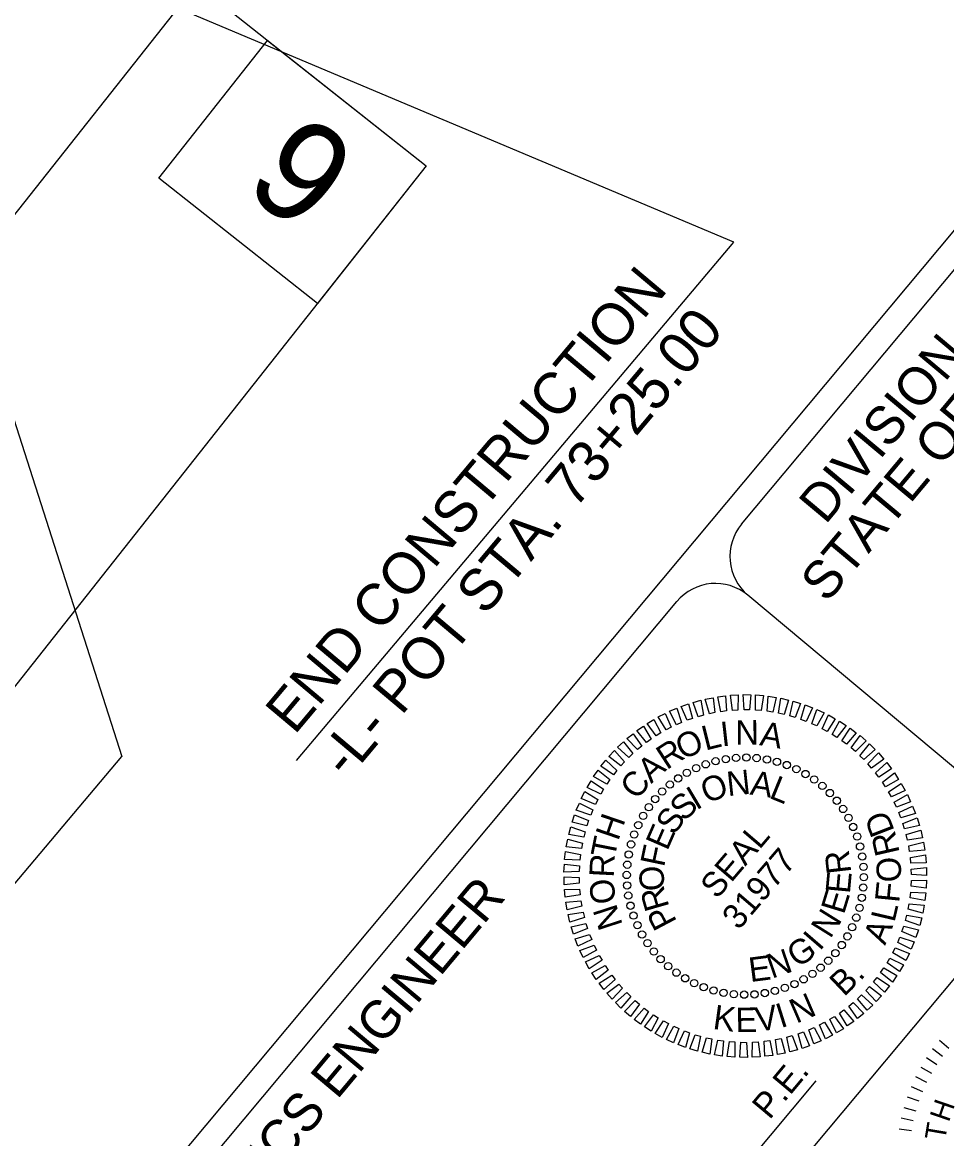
# Model space of a CAD drawing. Extents: x 555292 to 2368606, y 503623 to 1171444.
# Drawn here: x 2362561 to 2363476, y 1164815 to 1165919 of the extents above; entities that cross this region are included whole.
import ezdxf

# ---------------------------------------------------------------- set-up
doc = ezdxf.new("R2010")
doc.units = 0
for name, color, linetype in [('Default', 7, 'Continuous'), ('Old_Level_21', 7, 'Continuous'), ('Prop Horizontal Alignment Station Label', 7, 'Continuous'), ('Sheet Title CELL', 7, 'Continuous')]:
    doc.layers.add(name, color=color, linetype=linetype)

msp = doc.modelspace()

# ---------------------------------------------------------------- linework, layer by layer
at = {"layer": 'Default'}
for points in [[(2363263.9, 1165238.4), (2363261.9, 1165253.4), (2363269.7, 1165253.7), (2363269.4, 1165238.8)], [(2363275.4, 1165238.9), (2363274.4, 1165254), (2363282.2, 1165253.8), (2363280.9, 1165238.9)], [(2363286.9, 1165238.6), (2363286.9, 1165253.7), (2363294.7, 1165253), (2363292.4, 1165238.2)], [(2363219.2, 1165228.6), (2363213.1, 1165242.4), (2363220.5, 1165244.9), (2363224.4, 1165230.5)], [(2363230.1, 1165232.2), (2363225, 1165246.4), (2363232.6, 1165248.4), (2363235.4, 1165233.7)], [(2363241.2, 1165235.1), (2363237.1, 1165249.6), (2363244.8, 1165251), (2363246.6, 1165236.2)], [(2363252.5, 1165237.1), (2363249.4, 1165251.9), (2363257.2, 1165252.8), (2363258, 1165237.9)], [(2363298.3, 1165237.5), (2363299.4, 1165252.6), (2363307.1, 1165251.3), (2363303.8, 1165236.7)], [(2363309.6, 1165235.6), (2363311.7, 1165250.5), (2363319.4, 1165248.7), (2363315, 1165234.4)], [(2363320.8, 1165232.9), (2363323.9, 1165247.7), (2363331.4, 1165245.3), (2363326.1, 1165231.4)], [(2363331.7, 1165229.4), (2363335.9, 1165243.9), (2363343.2, 1165241.1), (2363336.9, 1165227.5)], [(2363198.3, 1165219.1), (2363190.4, 1165231.9), (2363197.4, 1165235.4), (2363203.2, 1165221.7)], [(2363208.6, 1165224.2), (2363201.6, 1165237.5), (2363208.8, 1165240.5), (2363213.7, 1165226.4)], [(2363342.4, 1165225.2), (2363347.6, 1165239.4), (2363354.6, 1165236), (2363347.4, 1165223)], [(2363352.7, 1165220.3), (2363358.9, 1165234), (2363365.7, 1165230.2), (2363357.6, 1165217.7)], [(2363179, 1165206.8), (2363169.3, 1165218.4), (2363175.8, 1165222.8), (2363183.5, 1165210)], [(2363188.4, 1165213.3), (2363179.6, 1165225.5), (2363186.3, 1165229.5), (2363193.1, 1165216.2)], [(2363362.7, 1165214.6), (2363369.8, 1165227.9), (2363376.4, 1165223.6), (2363367.4, 1165211.7)], [(2363372.3, 1165208.3), (2363380.3, 1165221), (2363386.5, 1165216.3), (2363376.7, 1165205)], [(2363170, 1165199.6), (2363159.5, 1165210.5), (2363165.7, 1165215.4), (2363174.2, 1165203.2)], [(2363381.4, 1165201.3), (2363390.3, 1165213.5), (2363396.1, 1165208.3), (2363385.6, 1165197.7)], [(2363153.6, 1165183.6), (2363141.7, 1165192.9), (2363147.1, 1165198.6), (2363157.3, 1165187.7)], [(2363161.5, 1165191.9), (2363150.3, 1165202), (2363156.1, 1165207.3), (2363165.5, 1165195.7)], [(2363390, 1165193.6), (2363399.7, 1165205.2), (2363405.2, 1165199.6), (2363393.9, 1165189.8)], [(2363146.3, 1165174.7), (2363133.8, 1165183.2), (2363138.8, 1165189.2), (2363149.7, 1165179.1)], [(2363398, 1165185.5), (2363408.5, 1165196.3), (2363413.6, 1165190.3), (2363401.7, 1165181.3)], [(2363139.6, 1165165.4), (2363126.6, 1165173), (2363131.1, 1165179.3), (2363142.7, 1165170)], [(2363405.5, 1165176.7), (2363416.7, 1165186.8), (2363421.3, 1165180.5), (2363408.8, 1165172.4)], [(2363412.3, 1165167.5), (2363424.2, 1165176.7), (2363428.4, 1165170.1), (2363415.3, 1165162.9)], [(2363133.6, 1165155.6), (2363120.1, 1165162.3), (2363124.2, 1165168.9), (2363136.4, 1165160.4)], [(2363418.4, 1165157.8), (2363431, 1165166.2), (2363434.7, 1165159.3), (2363421.2, 1165153)], [(2363128.3, 1165145.4), (2363114.3, 1165151.1), (2363117.9, 1165158.1), (2363130.7, 1165150.4)], [(2363423.9, 1165147.7), (2363437, 1165155.2), (2363440.2, 1165148.1), (2363426.3, 1165142.7)], [(2363123.7, 1165134.9), (2363109.4, 1165139.6), (2363112.5, 1165146.8), (2363125.8, 1165140)], [(2363428.6, 1165137.3), (2363442.2, 1165143.8), (2363445, 1165136.5), (2363430.7, 1165132.1)], [(2363119.9, 1165124.1), (2363105.2, 1165127.8), (2363107.8, 1165135.2), (2363121.6, 1165129.4)], [(2363116.8, 1165113), (2363101.9, 1165115.7), (2363104, 1165123.2), (2363118.1, 1165118.4)], [(2363432.6, 1165126.5), (2363446.7, 1165132.1), (2363448.9, 1165124.6), (2363434.3, 1165121.2)], [(2363114.5, 1165101.8), (2363099.5, 1165103.4), (2363101, 1165111.1), (2363115.5, 1165107.2)], [(2363435.9, 1165115.5), (2363450.3, 1165120.1), (2363452, 1165112.5), (2363437.2, 1165110.1)], [(2363438.4, 1165104.3), (2363453, 1165107.9), (2363454.2, 1165100.2), (2363439.3, 1165098.8)], [(2363113, 1165090.4), (2363097.9, 1165091), (2363098.9, 1165098.7), (2363113.6, 1165095.9)], [(2363440.1, 1165092.9), (2363454.9, 1165095.5), (2363455.5, 1165087.7), (2363440.6, 1165087.4)], [(2363112.3, 1165079), (2363097.2, 1165078.5), (2363097.7, 1165086.3), (2363112.5, 1165084.5)], [(2363440.9, 1165081.5), (2363456, 1165083), (2363456, 1165075.2), (2363441.1, 1165076)], [(2363112.4, 1165067.5), (2363097.3, 1165066), (2363097.3, 1165073.8), (2363112.2, 1165073)], [(2363441, 1165070), (2363456.1, 1165070.5), (2363455.6, 1165062.7), (2363440.8, 1165064.5)], [(2363113.2, 1165056), (2363098.4, 1165053.5), (2363097.8, 1165061.3), (2363112.7, 1165061.5)], [(2363440.3, 1165058.6), (2363455.4, 1165058), (2363454.4, 1165050.2), (2363439.7, 1165053.1)], [(2363114.9, 1165044.7), (2363100.3, 1165041.1), (2363099.1, 1165048.8), (2363114, 1165050.1)], [(2363438.8, 1165047.2), (2363453.8, 1165045.6), (2363452.3, 1165037.9), (2363437.8, 1165041.7)], [(2363117.4, 1165033.5), (2363103, 1165028.9), (2363101.3, 1165036.5), (2363116.1, 1165038.8)], [(2363436.5, 1165035.9), (2363451.4, 1165033.3), (2363449.3, 1165025.7), (2363435.2, 1165030.6)], [(2363120.6, 1165022.5), (2363106.6, 1165016.9), (2363104.4, 1165024.4), (2363119, 1165027.7)], [(2363433.4, 1165024.9), (2363448.1, 1165021.2), (2363445.5, 1165013.8), (2363431.7, 1165019.6)], [(2363124.7, 1165011.7), (2363111.1, 1165005.1), (2363108.3, 1165012.5), (2363122.6, 1165016.8)], [(2363429.6, 1165014.1), (2363443.9, 1165009.3), (2363440.8, 1165002.2), (2363427.5, 1165008.9)], [(2363129.4, 1165001.3), (2363116.3, 1164993.8), (2363113.1, 1165000.9), (2363127, 1165006.2)], [(2363425, 1165003.5), (2363439, 1164997.8), (2363435.4, 1164990.9), (2363422.6, 1164998.6)], [(2363134.9, 1164991.2), (2363122.3, 1164982.8), (2363118.6, 1164989.6), (2363132.1, 1164996)], [(2363419.7, 1164993.4), (2363433.2, 1164986.7), (2363429.1, 1164980), (2363416.9, 1164988.6)], [(2363141, 1164981.5), (2363129.1, 1164972.2), (2363124.9, 1164978.8), (2363138, 1164986.1)], [(2363413.7, 1164983.6), (2363426.7, 1164976), (2363422.2, 1164969.6), (2363410.6, 1164979)], [(2363147.8, 1164972.3), (2363136.6, 1164962.2), (2363132, 1164968.5), (2363144.5, 1164976.6)], [(2363155.3, 1164963.5), (2363144.8, 1164952.7), (2363139.7, 1164958.6), (2363151.6, 1164967.6)], [(2363407, 1164974.2), (2363419.5, 1164965.8), (2363414.5, 1164959.7), (2363403.6, 1164969.9)], [(2363163.3, 1164955.3), (2363153.6, 1164943.8), (2363148.1, 1164949.4), (2363159.4, 1164959.2)], [(2363391.8, 1164957.1), (2363403, 1164946.9), (2363397.2, 1164941.7), (2363387.8, 1164953.2)], [(2363399.7, 1164965.4), (2363411.6, 1164956.1), (2363406.2, 1164950.4), (2363396, 1164961.3)], [(2363171.9, 1164947.7), (2363163, 1164935.5), (2363157.2, 1164940.7), (2363167.7, 1164951.3)], [(2363383.3, 1164949.3), (2363393.8, 1164938.4), (2363387.6, 1164933.6), (2363379.1, 1164945.8)], [(2363181, 1164940.7), (2363173, 1164927.9), (2363166.8, 1164932.7), (2363176.6, 1164944)], [(2363190.6, 1164934.4), (2363183.5, 1164921.1), (2363176.9, 1164925.4), (2363185.9, 1164937.3)], [(2363364.9, 1164935.7), (2363373.7, 1164923.5), (2363367, 1164919.5), (2363360.2, 1164932.8)], [(2363374.3, 1164942.2), (2363384, 1164930.6), (2363377.5, 1164926.2), (2363369.8, 1164939)], [(2363200.6, 1164928.7), (2363194.4, 1164914.9), (2363187.6, 1164918.8), (2363195.7, 1164931.3)], [(2363210.9, 1164923.8), (2363205.7, 1164909.6), (2363198.7, 1164913), (2363205.9, 1164926)], [(2363344.7, 1164924.8), (2363351.7, 1164911.4), (2363344.5, 1164908.4), (2363339.6, 1164922.5)], [(2363355, 1164929.9), (2363362.9, 1164917.1), (2363355.9, 1164913.6), (2363350.1, 1164927.3)], [(2363221.6, 1164919.5), (2363217.4, 1164905), (2363210.1, 1164907.9), (2363216.4, 1164921.4)], [(2363232.5, 1164916.1), (2363229.4, 1164901.3), (2363221.9, 1164903.7), (2363227.2, 1164917.6)], [(2363243.7, 1164913.4), (2363241.5, 1164898.4), (2363233.9, 1164900.3), (2363238.3, 1164914.5)], [(2363255, 1164911.5), (2363253.9, 1164896.4), (2363246.2, 1164897.7), (2363249.5, 1164912.3)], [(2363300.8, 1164911.8), (2363303.9, 1164897), (2363296.1, 1164896.2), (2363295.3, 1164911.1)], [(2363312.1, 1164913.9), (2363316.2, 1164899.4), (2363308.5, 1164898), (2363306.7, 1164912.8)], [(2363323.2, 1164916.8), (2363328.3, 1164902.6), (2363320.7, 1164900.6), (2363317.9, 1164915.3)], [(2363334.1, 1164920.4), (2363340.2, 1164906.6), (2363332.8, 1164904.1), (2363328.9, 1164918.5)], [(2363266.4, 1164910.4), (2363266.4, 1164895.3), (2363258.6, 1164896), (2363260.9, 1164910.8)], [(2363277.9, 1164910), (2363278.9, 1164895), (2363271.1, 1164895.2), (2363272.4, 1164910.1)], [(2363289.4, 1164910.5), (2363291.4, 1164895.6), (2363283.6, 1164895.2), (2363283.9, 1164910.2)]]:
    msp.add_lwpolyline(points, close=True, dxfattribs=at)
for centre in [(2363237.5, 1165185.1), (2363247.3, 1165188.1), (2363257.3, 1165190.2), (2363267.5, 1165191.4), (2363277.7, 1165191.8), (2363287.9, 1165191.3), (2363298.1, 1165189.8), (2363308, 1165187.5), (2363317.8, 1165184.4), (2363218.9, 1165176.6), (2363228, 1165181.3), (2363327.2, 1165180.4), (2363336.2, 1165175.5), (2363202.1, 1165165), (2363210.2, 1165171.2), (2363344.8, 1165170), (2363352.9, 1165163.7), (2363187.5, 1165150.7), (2363194.5, 1165158.2), (2363360.4, 1165156.7), (2363181.2, 1165142.6), (2363367.2, 1165149.1), (2363373.4, 1165140.9), (2363175.6, 1165134.1), (2363378.8, 1165132.2), (2363170.8, 1165125), (2363383.4, 1165123.1), (2363166.8, 1165115.6), (2363387.3, 1165113.6), (2363161.3, 1165095.9), (2363163.6, 1165105.9), (2363390.2, 1165103.8), (2363159.9, 1165085.8), (2363392.4, 1165093.8), (2363159.3, 1165075.6), (2363393.6, 1165083.6), (2363394, 1165073.4), (2363159.7, 1165065.3), (2363393.4, 1165063.2), (2363160.9, 1165055.2), (2363392, 1165053.1), (2363163.1, 1165045.2), (2363389.7, 1165043.1), (2363166, 1165035.4), (2363386.5, 1165033.4), (2363169.9, 1165025.9), (2363382.5, 1165023.9), (2363174.5, 1165016.8), (2363179.9, 1165008.1), (2363377.7, 1165014.9), (2363186.1, 1164999.9), (2363365.8, 1164998.3), (2363372.1, 1165006.3), (2363192.9, 1164992.3), (2363200.4, 1164985.3), (2363358.8, 1164990.8), (2363208.5, 1164979), (2363343.1, 1164977.8), (2363351.2, 1164983.9), (2363217.1, 1164973.4), (2363226.1, 1164968.6), (2363235.5, 1164964.6), (2363315.8, 1164963.9), (2363325.3, 1164967.7), (2363334.4, 1164972.4), (2363245.3, 1164961.4), (2363255.2, 1164959.1), (2363265.4, 1164957.7), (2363275.6, 1164957.2), (2363285.8, 1164957.5), (2363296, 1164958.8), (2363306, 1164960.9)]:
    msp.add_circle(centre, 3.63, dxfattribs=at)
at = {"layer": 'Old_Level_21'}
for p, q in [((2363468.8, 1164912.3), (2363478.1, 1164904.4)), ((2363462, 1164903.8), (2363471.9, 1164896.5)), ((2363455.9, 1164894.9), (2363466.1, 1164888.2)), ((2363450.2, 1164885.6), (2363460.8, 1164879.6)), ((2363445.2, 1164876.1), (2363456.1, 1164870.6)), ((2363440.7, 1164866.2), (2363452, 1164861.4)), ((2363433.6, 1164845.7), (2363445.3, 1164842.4)), ((2363436.8, 1164856.1), (2363448.4, 1164852)), ((2363430.9, 1164835.2), (2363442.9, 1164832.6)), ((2363428.9, 1164824.5), (2363441, 1164822.7))]:
    msp.add_line(p, q, dxfattribs=at)
at = {"layer": 'Prop Horizontal Alignment Station Label'}
for p, q in [((2362365.6, 1166110.7), (2362659.7, 1165192.7)), ((2363265.2, 1165701.7), (2362427.6, 1166054.4)), ((2362832.5, 1165188.9), (2363265.2, 1165701.7)), ((2362128.7, 1164563.4), (2362659.7, 1165192.7))]:
    msp.add_line(p, q, dxfattribs=at)
at = {"layer": 'Sheet Title CELL'}
for p, q in [((2359196.5, 1160588.2), (2363751.8, 1166034.2)), ((2363273, 1165422.8), (2363771, 1166018.2)), ((2362568, 1164579.9), (2363208.9, 1165346.1)), ((2363892.9, 1164839.1), (2363279.3, 1165352.4)), ((2362878.1, 1164249.5), (2363586, 1165095.8)), ((2362884, 1164318.8), (2363346.8, 1164872.1))]:
    msp.add_line(p, q, dxfattribs=at)
for points in [[(2362362.7, 1165487.8), (2361186.1, 1166418.1), (2361837.3, 1167241.7), (2363013.9, 1166311.4)], [(2362309.6, 1164953.5), (2361133, 1165883.8), (2361784.3, 1166707.5), (2362960.9, 1165777.1)], [(2362804, 1165901.2), (2362960.9, 1165777.1), (2362853.3, 1165641), (2362696.3, 1165765.1)]]:
    msp.add_lwpolyline(points, close=True, dxfattribs=at)
for centre, start, end in [((2363311.4, 1165390.7), 140.0895, 230.0895), ((2363247.2, 1165314), 50.0895, 140.0895)]:
    msp.add_arc(centre, 50, start, end, dxfattribs=at)

# ---------------------------------------------------------------- texts
at = {"layer": 'Default'}
for s, height, rotation, p in [('9', 100, 321.6667, (2362778, 1165754.5)), ('L', 24.2, 13.9543, (2363237.1, 1165198.6)), ('I', 24.2, 6.4892, (2363253.5, 1165202.7)), ('N', 24.2, 0.5492, (2363266.9, 1165204.4)), ('A', 24.2, 350.3388, (2363290.1, 1165204.1)), ('O', 24.2, 24.6795, (2363214.7, 1165189.1)), ('R', 24.2, 32.8881, (2363198.9, 1165179.1)), ('A', 24.2, 41.9356, (2363183.5, 1165165.5)), ('C', 24.2, 51.4407, (2363169.7, 1165148.9)), ('N', 24.2, 6.2204, (2363259.5, 1165153.5)), ('A', 24.2, 351.1704, (2363280.6, 1165155.3)), ('O', 24.2, 22.0292, (2363238.6, 1165145.9)), ('L', 24.2, 337.8345, (2363299.2, 1165152.2)), ('S', 24.2, 42.7436, (2363215.8, 1165127.8)), ('I', 24.2, 30.7847, (2363228.2, 1165139.2)), ('H', 24.2, 71.0799, (2363150.9, 1165108.6)), ('S', 24.2, 54.7026, (2363206.1, 1165114.1)), ('D', 24.2, 111.1793, (2363424.7, 1165119.3)), ('E', 24.2, 66.4648, (2363199.5, 1165098.8)), ('T', 24.2, 78.8691, (2363147.4, 1165091.3)), ('SEAL', 24.19, 49.4789, (2363248.6, 1165050.9)), ('R', 24.2, 102.9707, (2363429.6, 1165097.7)), ('F', 24.2, 78.1427, (2363196.2, 1165082.7)), ('31977', 24.19, 49.4789, (2363270.1, 1165020.3)), ('R', 24.2, 96.5218, (2363381.6, 1165078)), ('R', 24.2, 87.0778, (2363146.4, 1165072.7)), ('O', 24.2, 92.2455, (2363431.2, 1165068.8)), ('O', 24.2, 93.9515, (2363197, 1165060.5)), ('E', 24.2, 84.7596, (2363380.1, 1165056.5)), ('O', 24.2, 97.8029, (2363149, 1165048.4)), ('F', 24.2, 84.3228, (2363428.9, 1165047.6)), ('R', 24.2, 106.051, (2363201.7, 1165044.1)), ('E', 24.2, 72.9973, (2363374.2, 1165035.8)), ('N', 24.2, 108.0134, (2363155.6, 1165026.2)), ('L', 24.2, 76.8577, (2363424.2, 1165028)), ('P', 24.2, 117.8132, (2363209.5, 1165029.5)), ('N', 24.2, 57.9473, (2363360.8, 1165011.8)), ('A', 24.2, 67.8102, (2363415, 1165005.4)), ('G', 24.2, 34.1418, (2363328.4, 1164983.1)), ('I', 24.2, 49.1918, (2363350.3, 1164999.7)), ('N', 24.2, 19.0917, (2363302.9, 1164972.9)), ('E', 24.2, 7.3295, (2363281.6, 1164969.6)), ('B', 24.2, 43.4988, (2363374.3, 1164954.6)), ('.', 24.2, 51.8409, (2363390.7, 1164970)), ('N', 24.2, 23.4021, (2363327.1, 1164928.3)), ('K', 24.2, 352.0926, (2363243.8, 1164923.4)), ('E', 24.2, 0.797, (2363267.1, 1164920.1)), ('V', 24.2, 8.7768, (2363288.6, 1164920.3)), ('I', 24.2, 17.4621, (2363311.7, 1164923.9))]:
    msp.add_text(s, height=height, rotation=rotation, dxfattribs=at).set_placement(p)
at = {"layer": 'Old_Level_21'}
for s, rotation, p in [('H', 71.0773, (2363478, 1164830.3)), ('T', 80.5093, (2363474.3, 1164812.1))]:
    msp.add_text(s, height=20.4, rotation=rotation, dxfattribs=at).set_placement(p)
at = {"layer": 'Prop Horizontal Alignment Station Label'}
for s, p in [('END CONSTRUCTION', (2362830.6, 1165213.3)), ('-L- POT STA. 73+25.00', (2362883.2, 1165169.1))]:
    msp.add_text(s, height=41.248, rotation=49.9796, dxfattribs=at).set_placement(p)
at = {"layer": 'Sheet Title CELL'}
for s, height, p in [('STATE OF NORTH CAROLINA', 37.497, (2363357.4, 1165343.8)), ('DIVISION OF HIGHWAYS', 37.497, (2363355.9, 1165421.4)), (' HYDRAULICS ENGINEER', 37.5, (2362647.4, 1164583.2)), ('P.E.', 25, (2363300.6, 1164832.7))]:
    msp.add_text(s, height=height, rotation=50.0895, dxfattribs=at).set_placement(p)

doc.saveas('drawing.dxf')
